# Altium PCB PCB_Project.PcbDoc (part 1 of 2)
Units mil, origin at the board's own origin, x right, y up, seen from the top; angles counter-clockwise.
Board outline 2890 x 2480 mil, 2 copper layers (Top Layer, Bottom Layer), stack 62 mil thick; 127 components, 89 nets, 394 pads, 87 vias.
Unrouted connection lines stored in the file: 1.
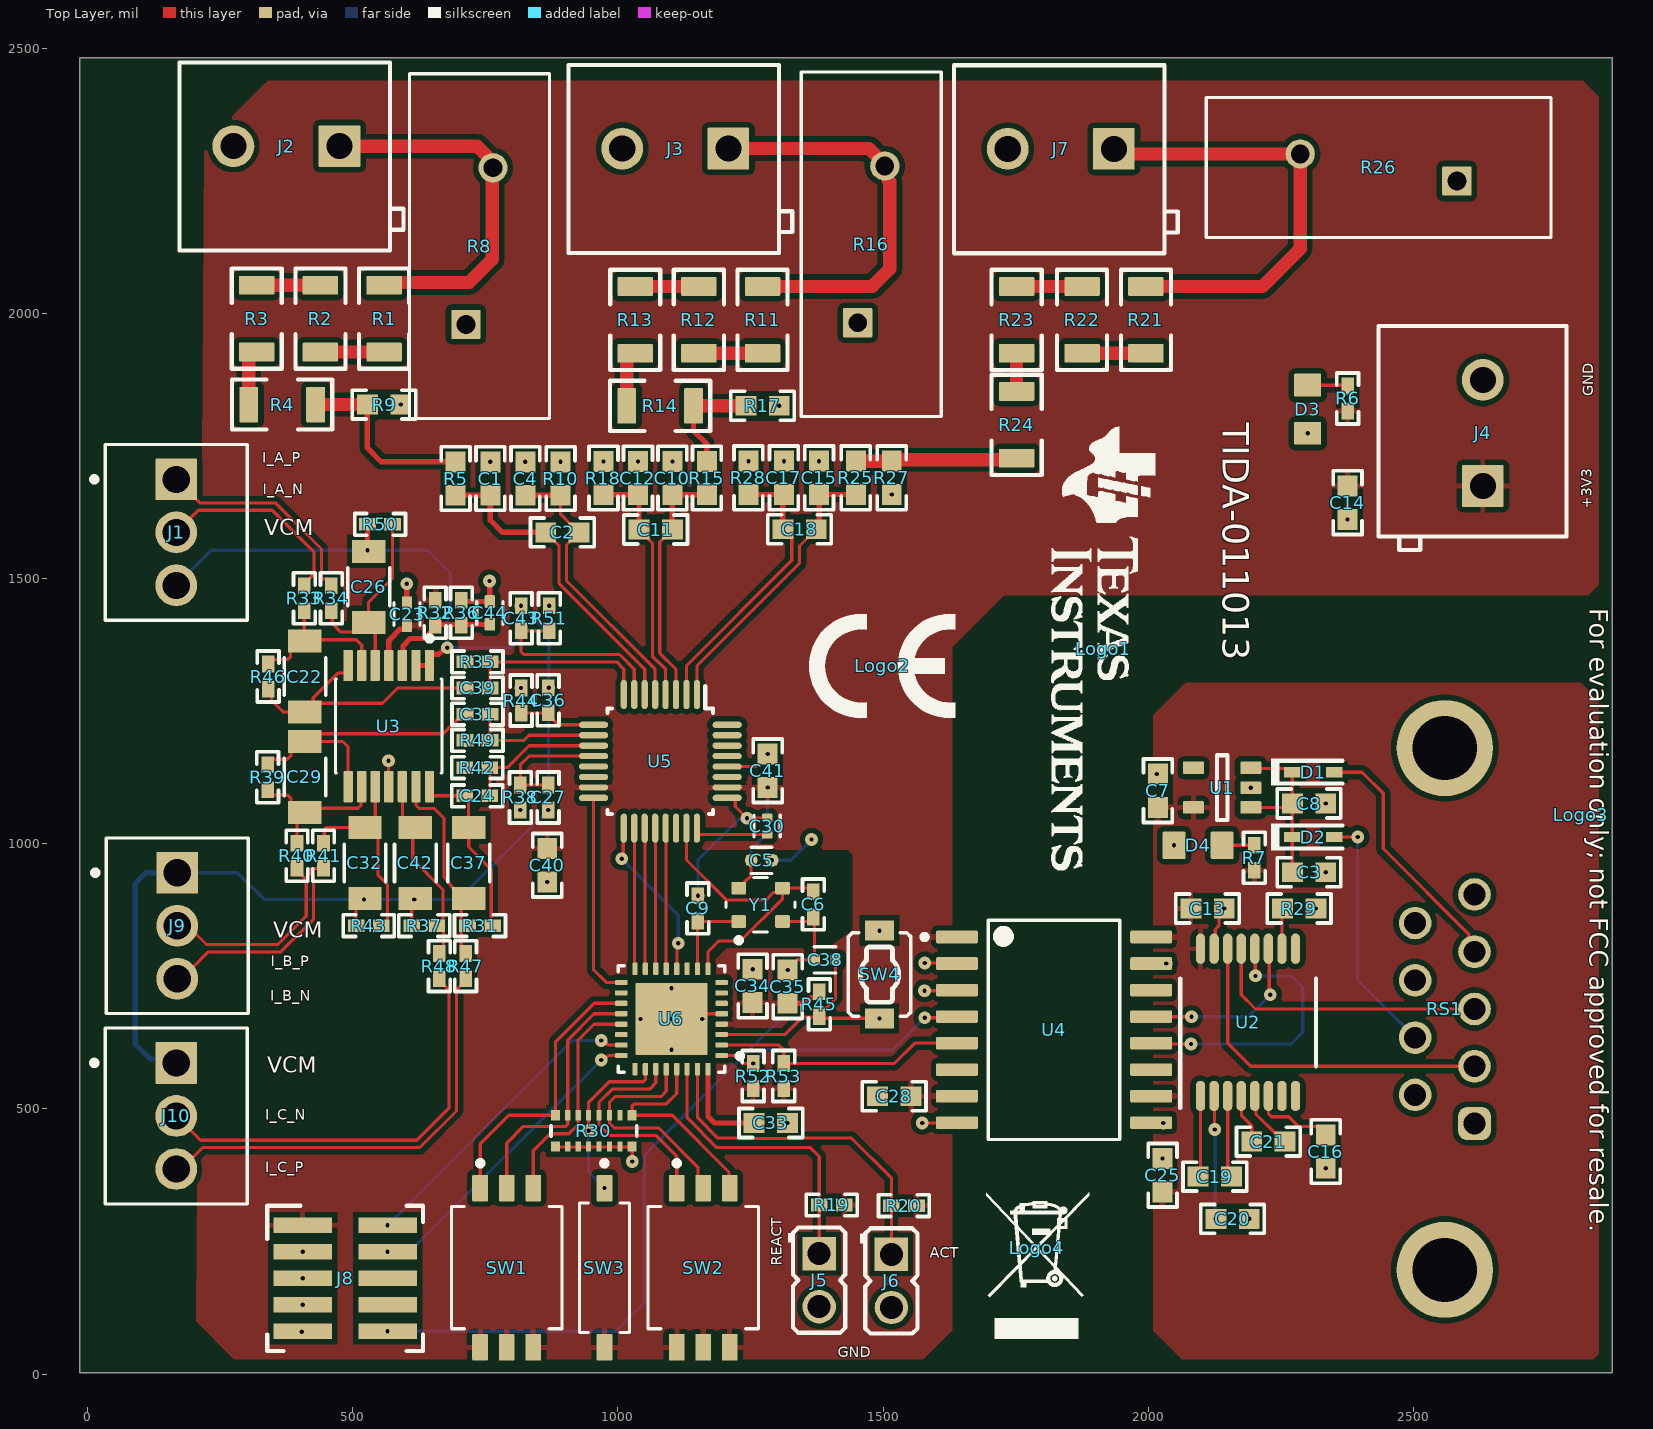
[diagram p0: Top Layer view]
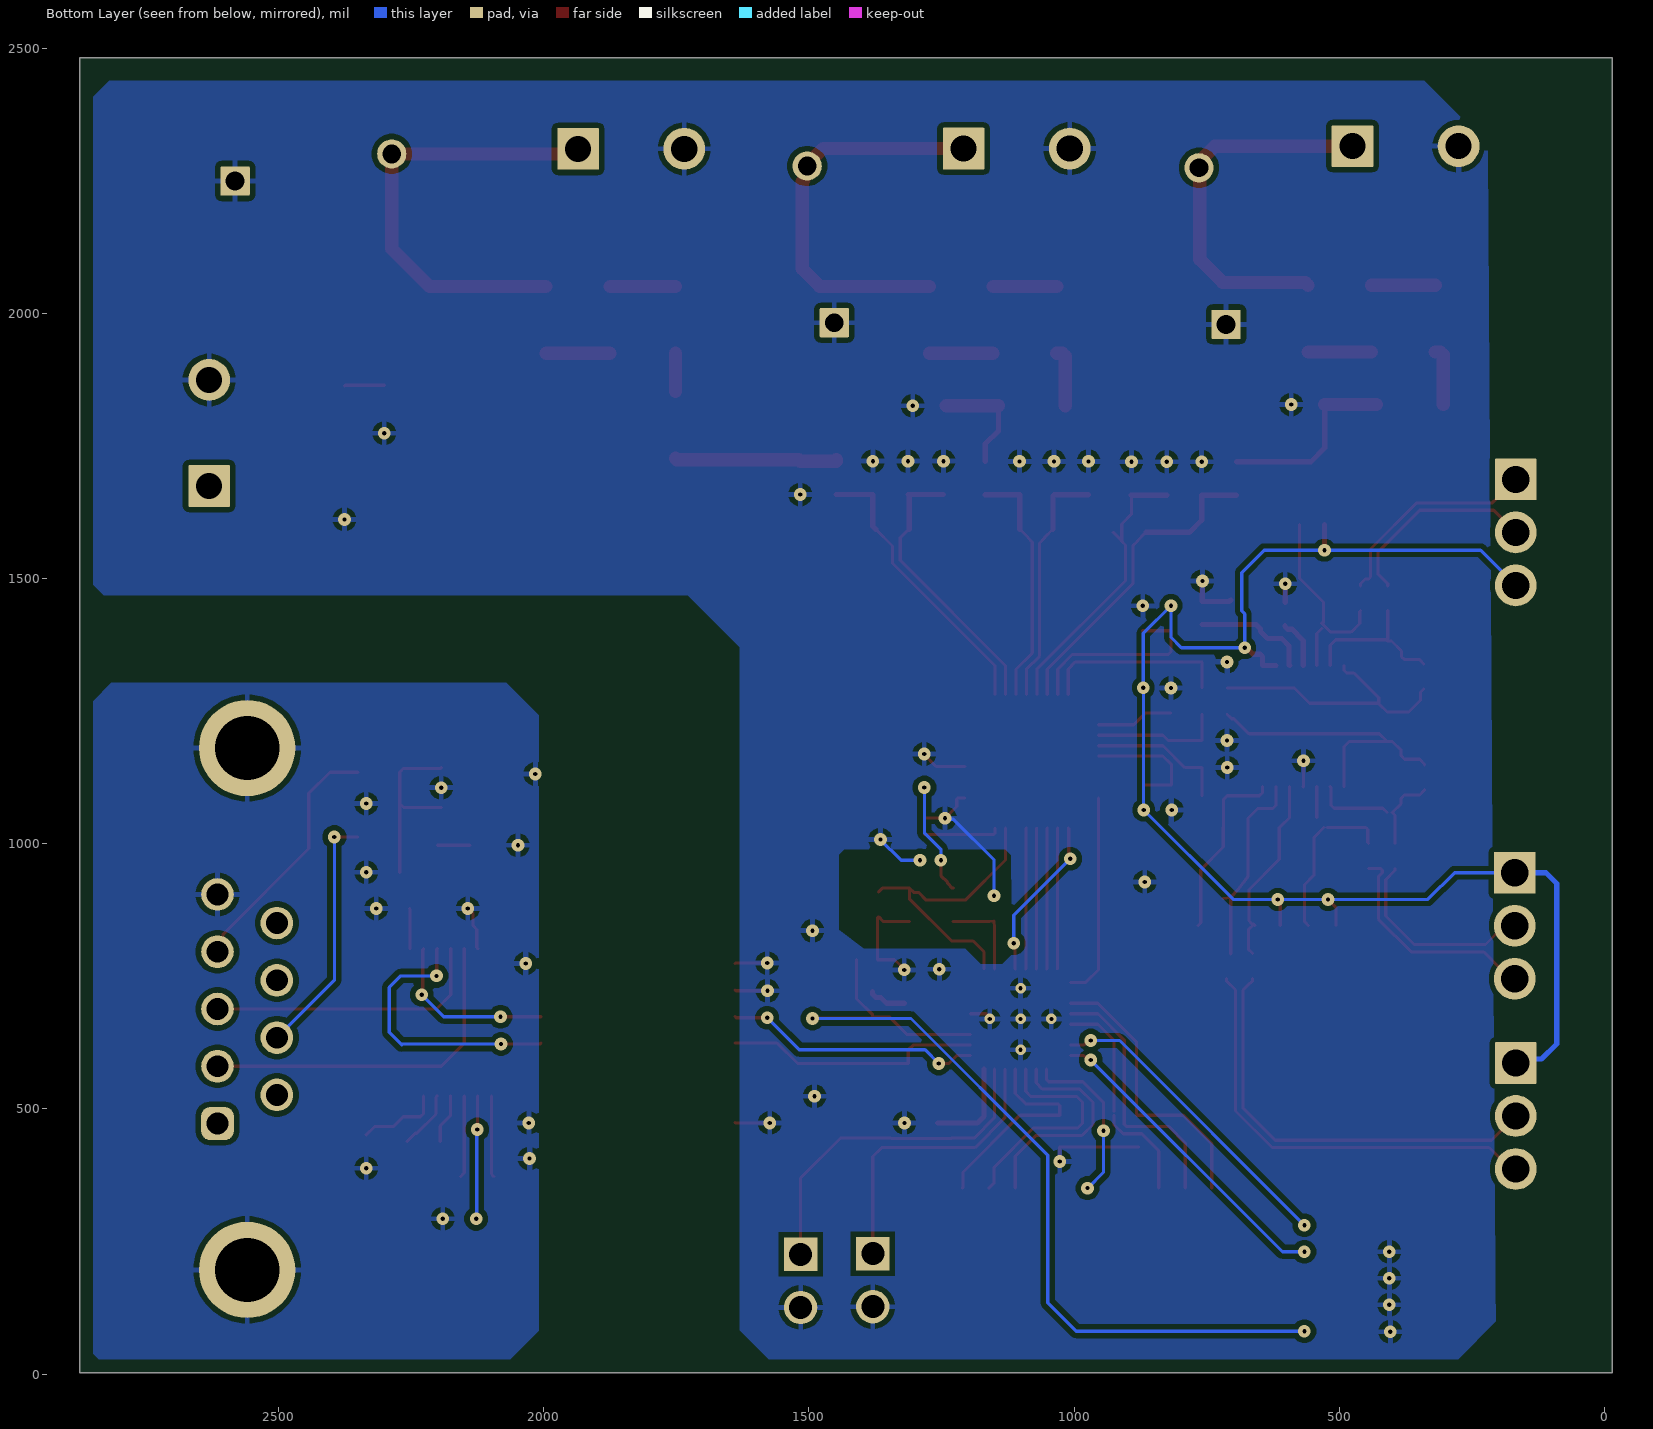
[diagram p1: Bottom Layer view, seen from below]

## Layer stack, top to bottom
Top Solder: solder mask 0.4, Solder Resist, Dk 3.5
Top Layer: signal copper 1.4
Dielectric1: core 59.2, FR-4 High Tg, Dk 4.8
Bottom Layer: signal copper 1.4
Bottom Solder: solder mask 0.4, Solder Resist, Dk 3.5

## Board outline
-15,2 -15,2482 2875,2482 2875,2

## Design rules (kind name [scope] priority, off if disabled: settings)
AcuteAngle [All] p1: minimum=4.50000000000000E+0001 checktracksonly=FALSE
AssemblyTestPointUsage [All] p1: valid=2
BoardOutlineClearance BoardOutlineClearance_MountingHoles [OnCopper and InComponentClass('Mounting Holes')] p1: gap=39.37 ignorepadtopadclearanceinfootprint=FALSE
BoardOutlineClearance BoardOutlineClearance_Poly [OnCopper and IsPoly] p2: gap=25 ignorepadtopadclearanceinfootprint=FALSE
BoardOutlineClearance [OnCopper and Not InComponentClass('Logo') and not InComponentClass('FiducialMark') and not InRegion(1000,500,4000,800) and not InPoly] p3: gap=40 ignorepadtopadclearanceinfootprint=FALSE
Clearance Clearance_Keepouts [((IsTrack Or IsArc) And Not InPoly) And IsFree and IsKeepOut vs ((IsTrack Or IsArc) And Not InPoly) And IsFree and IsKeepOut] p1: gap=0 ignorepadtopadclearanceinfootprint=FALSE
Clearance Clearance_Poly [InPolygon] p2: gap=10 ignorepadtopadclearanceinfootprint=TRUE
Clearance Clearance_FiducialMark [IsKeepOut and InComponentClass('FiducialMark') vs IsPad and InComponentClass('FiducialMark')] p3: gap=0 ignorepadtopadclearanceinfootprint=FALSE
Clearance [All] p4: gap=7.87 ignorepadtopadclearanceinfootprint=TRUE
ComponentClearance ComponentClearance_MountingHoles_FiducialMarks [InComponentClass('Mounting Holes') vs InComponentClass('FiducialMark')] p1: gap=50 collisioncheckmode=3 verticalgap=10 showdistances=FALSE
ComponentClearance ComponentClearance_Shunt [InComponentClass('Header') vs InComponentClass('Shunt')] p2: gap=0 collisioncheckmode=3 verticalgap=0 showdistances=FALSE
ComponentClearance ComponentClearance_Logo [InComponentClass('Logo')] p3: gap=30 collisioncheckmode=3 verticalgap=10 showdistances=FALSE
ComponentClearance ComponentClearance_ScrewToNut [(HasFootprint('NY PMS 440 0025 PH')) vs (HasFootprint('Keystone_1902C'))] p4: gap=5 collisioncheckmode=3 verticalgap=10 showdistances=FALSE
ComponentClearance ComponentClearance_MountingHoles [InComponentClass('Mounting Holes')] p5: gap=100 collisioncheckmode=3 verticalgap=100000 showdistances=FALSE
ComponentClearance ComponentClearance_SmallPassives [HasFootprint('0201*') or HasFootprint('0402*') or HasFootprint('0508') or HasFootprint('0603*') or HasFootprint('0612') or HasFootprint('0805*') or HasFootprint('0815*') or HasFootprint('0830*') or HasFootprint('1206*') or HasFootprint('1210*') or HasFootprint('1808*') or HasFootprint('1812*') or HasFootprint('1825*') or HasFootprint('2010*') or HasFootprint('2220*') or HasFootprint('2225*') or HasFootprint('2512*') or HasFootprint('2728*') or HasFootprint('3518*') vs HasFootprint('0201*') or HasFootprint('0402*') or HasFootprint('0508') or HasFootprint('0603*') or HasFootprint('0612') or HasFootprint('0805*') or HasFootprint('0815*') or HasFootprint('0830*') or HasFootprint('1206*') or HasFootprint('1210*') or HasFootprint('1808*') or HasFootprint('1812*') or HasFootprint('1825*') or HasFootprint('2010*') or HasFootprint('2220*') or HasFootprint('2225*') or HasFootprint('2512*') or HasFootprint('2728*') or HasFootprint('3518*')] p6: gap=14.96 collisioncheckmode=3 verticalgap=10 showdistances=FALSE
ComponentClearance ComponentClearance_THtoSMT [IsThruComponent vs IsSMTComponent] p7: gap=30 collisioncheckmode=3 verticalgap=30 showdistances=FALSE
ComponentClearance ComponentClearance_THtoTH [IsThruComponent vs IsThruComponent] p8: gap=20 collisioncheckmode=3 verticalgap=30 showdistances=FALSE
ComponentClearance [All] p9: gap=20 collisioncheckmode=3 verticalgap=10 showdistances=FALSE
DiffPairsRouting [All] p1: maxlimit=100 minlimit=10 mostfreqgap=10 toplayer_minwidth=15 toplayer_maxwidth=15 toplayer_prefwidth=15 bottomlayer_minwidth=15 bottomlayer_maxwidth=15 bottomlayer_prefwidth=15 maxuncoupledlength=1000
FabricationTestPointUsage TestPointUsage [All] p1: valid=2 allowmultiple=FALSE
FabricationTestpoint Testpoint [All] p1: side=3 testpointundercomponent=TRUE minsize=40 maxsize=100 preferedsize=60 minholesize=0 maxholesize=40 preferedholesize=32 testpointgrid=1 allowsidetop=TRUE allowsidebottom=TRUE usegrid=TRUE gridtolerance=0.01
FanoutControl Fanout_LCC [IsLCC] p1: bgadir=Out bgaviamode=Centered fanoutstyle=Auto fanoutdirection=Alternating viagrid=1 // Fanout_LCC (Default Rule)
FanoutControl Fanout_BGA [IsBGA] p2: bgadir=Out bgaviamode=Centered fanoutstyle=Auto fanoutdirection=Alternating viagrid=1 // Fanout_BGA (Default Rule)
FanoutControl Fanout_Default [All] p4: bgadir=Out bgaviamode=Centered fanoutstyle=Auto fanoutdirection=Alternating viagrid=1 // Fanout_Default (Default Rule)
FanoutControl Fanout_Small [(CompPinCount < 5)] p5: bgadir=Out bgaviamode=Centered fanoutstyle=Auto fanoutdirection=OutThenIn viagrid=1 // Fanout_Small (Default Rule)
HoleSize [All] p1: absolutevalues=TRUE maxlimit=251 minlimit=7.87 maxpercent=80.000 minpercent=20.000
MinimumAnnularRing MinimumAnnularRing_ThermalPadVias [IsVia and InAnyComponent] p1: minimumring=5.91
MinimumAnnularRing [All] p2: minimumring=7.87
MinimumSolderMaskSliver MinimumSolderMaskSliver_Logo [InComponentClass('Logo') vs InComponentClass('Logo')] p1: minsoldermaskwidth=0.7
MinimumSolderMaskSliver [All] p2: minsoldermaskwidth=3.94
PlaneConnect [All] p1: planeconnectstyle=Relief reliefexpansion=10 reliefentries=4 reliefconductorwidth=10 reliefairgap=10
PolygonConnect [All] p1: connectstyle=Relief reliefconductorwidth=10 reliefentries=4 polygonreliefangle="90 Angle" airgapwidth=10
RoutingVias ThermalPadVias [IsVia and InAnyComponent] p1: holewidth=7.87 width=19.68 viastyle="Through Hole" minholewidth=7.87 minwidth=19.68 maxholewidth=12.99 maxwidth=23.62
RoutingVias [All] p2: holewidth=16 width=34 viastyle="Through Hole" minholewidth=7.87 minwidth=24 maxholewidth=40 maxwidth=65
SilkToBoardRegionClearance [Not ((IsComment or IsDesignator) And (Hide <> 'False')) and not InRegion(1000,500,4000,800)] p1:
SilkToSilkClearance SilkToSilkClearance_Pb-FreeLogo [(HasFootprint('Pb-Free_Overlay_Medium') OR HasFootprint('Pb-Free_Overlay_Small')) vs (HasFootprint('Pb-Free_Overlay_Medium') OR HasFootprint('Pb-Free_Overlay_Small'))] p1: silktosilkclearance=0
SilkToSilkClearance [All] p2: silktosilkclearance=3.94
SilkToSolderMaskClearance SilkToComponentPadClearance [(IsPad or IsFill or IsRegion) and InAnycomponent] p1: minsilkscreentomaskgap=5 clearancetoexposedcopper=TRUE
SilkToSolderMaskClearance "Silk to Solder Mask Opening" [All] p2: minsilkscreentomaskgap=3.94 clearancetoexposedcopper=FALSE
SolderMaskExpansion [All] p1: expansion=1.97 istentingtop=FALSE
SupplyNets "Schematic Supply Nets_45" [InNet('VG2')] p1: voltage=0.000
SupplyNets "Schematic Supply Nets_44" [InNet('VG4')] p2: voltage=0.000
SupplyNets "Schematic Supply Nets_43" [InNet('V_Phase_A_P')] p3: voltage=0.000
SupplyNets "Schematic Supply Nets_42" [InNet('VG1')] p4: voltage=0.000
SupplyNets "Schematic Supply Nets_41" [InNet('IN_Phase_C')] p5: voltage=0.000
SupplyNets "Schematic Supply Nets_40" [InNet('nRST')] p6: voltage=0.000
SupplyNets "Schematic Supply Nets_39" [InNet('V_Phase_B_N')] p7: voltage=0.000
SupplyNets "Schematic Supply Nets_38" [InNet('V_Phase_C_P')] p8: voltage=0.000
SupplyNets "Schematic Supply Nets_37" [InNet('Serial_RX')] p9: voltage=0.000
SupplyNets "Schematic Supply Nets_36" [InNet('RS232_PORT_DTR')] p10: voltage=0.000
SupplyNets "Schematic Supply Nets_35" [InNet('HFXOUT')] p11: voltage=0.000
SupplyNets "Schematic Supply Nets_34" [InNet('Serial_RX_ISO')] p12: voltage=0.000
SupplyNets "Schematic Supply Nets_33" [InNet('VCM')] p13: voltage=0.000
SupplyNets "Schematic Supply Nets_32" [InNet('SPI_SCK')] p14: voltage=0.000
SupplyNets "Schematic Supply Nets_31" [InNet('IP_Phase_B')] p15: voltage=0.000
SupplyNets "Schematic Supply Nets_30" [InNet('V_Phase_B_P')] p16: voltage=0.000
SupplyNets "Schematic Supply Nets_29" [InNet('Meter_TX_PC_RX')] p17: voltage=0.000
SupplyNets "Schematic Supply Nets_28" [InNet('ADS_SYNC_RESET')] p18: voltage=0.000
SupplyNets "Schematic Supply Nets_27" [InNet('Serial_TX')] p19: voltage=0.000
SupplyNets "Schematic Supply Nets_26" [InNet('VCC_ISO_RS')] p20: voltage=0.000
SupplyNets "Schematic Supply Nets_25" [InNet('IG1')] p21: voltage=0.000
SupplyNets "Schematic Supply Nets_24" [InNet('HFXIN')] p22: voltage=0.000
SupplyNets "Schematic Supply Nets_22" [InNet('IP_Phase_C')] p23: voltage=0.000
SupplyNets "Schematic Supply Nets_21" [InNet('IG2')] p24: voltage=0.000
SupplyNets "Schematic Supply Nets_20" [InNet('M0_CLKOUT')] p25: voltage=0.000
SupplyNets "Schematic Supply Nets_19" [InNet('V_Phase_A_N')] p26: voltage=0.000
SupplyNets "Schematic Supply Nets_18" [InNet('VCC')] p27: voltage=0.000
SupplyNets "Schematic Supply Nets_17" [InNet('ADS_DIN_MSP_DOUT')] p28: voltage=0.000
SupplyNets "Schematic Supply Nets_16" [InNet('IP_Phase_A')] p29: voltage=0.000
SupplyNets "Schematic Supply Nets_15" [InNet('ADS_DOUT_MSP_DIN')] p30: voltage=0.000
SupplyNets "Schematic Supply Nets_14" [InNet('TPS709_IN')] p31: voltage=0.000
SupplyNets "Schematic Supply Nets_13" [InNet('GND_ISO_RS')] p32: voltage=0.000
SupplyNets "Schematic Supply Nets_12" [InNet('REACT')] p33: voltage=0.000
SupplyNets "Schematic Supply Nets_11" [InNet('SW_INT')] p34: voltage=0.000
SupplyNets "Schematic Supply Nets_10" [InNet('IN_Phase_A')] p35: voltage=0.000
SupplyNets "Schematic Supply Nets_9" [InNet('RS232_PORT_RTS')] p36: voltage=0.000
SupplyNets "Schematic Supply Nets_8" [InNet('IN_Phase_B')] p37: voltage=0.000
SupplyNets "Schematic Supply Nets_7" [InNet('Meter_RX_PC_TX')] p38: voltage=0.000
SupplyNets "Schematic Supply Nets_6" [InNet('Serial_TX_ISO')] p39: voltage=0.000
SupplyNets "Schematic Supply Nets_5" [InNet('ACT')] p40: voltage=0.000
SupplyNets "Schematic Supply Nets_4" [InNet('IG4')] p41: voltage=0.000
SupplyNets "Schematic Supply Nets_3" [InNet('GND')] p42: voltage=0.000
SupplyNets "Schematic Supply Nets_2" [InNet('V_Phase_C_N')] p43: voltage=0.000
SupplyNets "Schematic Supply Nets_1" [InNet('ADS_CS')] p44: voltage=0.000
SupplyNets "Schematic Supply Nets" [InNet('ADS_DRDY')] p45: voltage=0.000
UnRoutedNet [All] p1: checkbadconnections=TRUE
Width [All] p1: maxlimit=100 minlimit=6 preferedwidth=10 checkconnectedcopper=TRUE
14 further rules are at their usual default settings.

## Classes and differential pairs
component class Header: J5 J6
component class Logo: Logo1
component class PCB_Project_Hardware: Logo1 Logo2 Logo3 Logo4

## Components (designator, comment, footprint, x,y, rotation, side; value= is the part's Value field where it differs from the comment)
C1 "GCM1885C2A100JA16D" 0603 759.46,1688.33 r90 top value=10pF
C2 "CGA3EANP02A682J080AC" 0603 895.3,1586.85 r0 top value=6800pF
C3 "GRT188R61H225KE13D" 0603 2303.04,946.1 r0 top value=2.2uF
C4 "GCM1885C2A100JA16D" 0603 825.41,1688.33 r270 top value=10pF
C5 "885012205018" FP-885012205018_0402-MFG 1270.79,968.56 r180 top value=100nF
C6 "GRM1555C1H150JA01D" 0402 1368.57,885.42 r270 top value=15pF
C7 "GRT188R61H225KE13D" 0603 2018.09,1099.66 r90 top value=2.2uF
C8 "CGA3E1X7R1E105M080AC" 0603 2303.04,1075.59 r0 top value=1uF
C9 "GRM1555C1H150JA01D" 0402 1150.82,877.89 r270 top value=15pF
C10 "GCM1885C2A100JA16D" 0603 1102.67,1689.21 r90 top value=10pF
C11 "CGA3EANP02A682J080AC" 0603 1071.17,1592.23 r180 top value=6800pF
C12 "GCM1885C2A100JA16D" 0603 1037.78,1689.21 r270 top value=10pF
C13 "CGA3E2X8R1E104K080AA" 0603 2111.64,877.64 r180 top value=0.1uF
C14 "GRM188R61A106KAALD" 0603 2375.71,1642.79 r270 top value=10uF
C15 "GCM1885C2A100JA16D" 0603 1379.33,1689.66 r90 top value=10pF
C16 "CGA3E2X8R1E104K080AA" 0603 2334.54,419.44 r90 top value=0.1uF
C17 "GCM1885C2A100JA16D" 0603 1312.91,1689.66 r270 top value=10pF
C18 "CGA3EANP02A682J080AC" 0603 1342.4,1592.68 r180 top value=6800pF
C19 "CGA3E2X8R1E104K080AA" 0603 2125.34,372.28 r180 top value=0.1uF
C20 "CGA3E2X8R1E104K080AA" 0603 2158.85,292.56 r180 top value=0.1uF
C21 "CGA3E2X8R1E104K080AA" 0603 2226.4,438.14 r180 top value=0.1uF
C22 "GRM31C5C1H683JA01L" 1206_180 409.87,1315.09 r90 top value=0.068uF
C23 "KAM05CR71A105MH" FP-KAM05CR71A105MH_0402-MFG 602.3,1432.91 r90 top value=1µF
C24 "GRM155R61E105KA12D" 0402 734.91,1090.19 r0 top value=1uF
C25 "C0603X104K3RACTU" 0603 2026.87,374.75 r90 top value=0.1uF
C26 "GRM31C5C1H683JA01L" 1206_180 530,1484.25 r270 top value=0.068uF
C27 "GRM155R61E105KA12D" 0402 868.54,1087.07 r90 top value=1uF
C28 "C0603X104K3RACTU" 0603 1520.81,523.56 r180 top value=0.1uF
C29 "GRM31C5C1H683JA01L" 1206_180 409.88,1125.62 r270 top value=0.068uF
C30 "CGA2B2X7R1C224K050BE" FP-CGA2B2X7R1C224K050BE_0402-MFG 1281.38,1033.1 r90 top value=220nF
C31 "GRM155R61E105KA12D" 0402 735.3,1244.23 r0 top value=1uF
C32 "GRM31C5C1H683JA01L" 1206_180 523.05,963.69 r90 top value=0.068uF
C33 "GRM188R61A474KA61D" 0603 1288.27,473.36 r180 top value=0.47uF
C34 "GRM188R61A106KAALD" 0603 1253.98,731.61 r270 top value=10uF
C35 "CGA3E2X8R1E104K080AA" 0603 1320,730.46 r270 top value=0.1uF
C36 "GRM155R61E105KA12D" 0402 868.54,1270.26 r270 top value=1uF
C37 "GRM31C5C1H683JA01L" 1206_180 718.68,963.69 r270 top value=0.068uF
C38 "885012205050" FP-885012205050_0402-MFG 1390.51,780.93 r0 top value=10nF
C39 "GRM155R61E105KA12D" 0402 735.3,1293.44 r0 top value=1uF
C40 "CGA3E1X7R1C105K080AC" 0603 866.71,959.28 r90 top value=1uF
C41 "CGA3E1X7R1C105K080AC" 0603 1282.28,1137.43 r270 top value=1uF
C42 "GRM31C5C1H683JA01L" 1206_180 618.05,963.69 r90 top value=0.068uF
C43 "GRM155R61E105KA12D" 0402 817.32,1425.03 r270 top value=1uF
C44 "KAM05CR71A105MH" FP-KAM05CR71A105MH_0402-MFG 758.53,1434.87 r90 top value=1µF
D1 "1N4148WT" Fairchild_SOD-523F 2310.92,1134.71 r0 top value=75V
D2 "1N4148WT" Fairchild_SOD-523F 2310.92,1012.48 r0 top value=75V
D3 "CMD17-21SRC/TR8" CMD17-21_Red 2300.44,1819.01 r270 top value=Red
D4 "CMD17-21SRC/TR8" CMD17-21_Red 2093.89,996.86 r180 top value=Red
J1 "691210910003" FP-691210910003_HDR3-MFG 167.21,1586.85 r270 top
J2 "ED120/2DS" On-Shore_ED120_2DS 375,2315 r180 top
J3 "ED120/2DS" On-Shore_ED120_2DS 1108.13,2310.43 r180 top
J4 "ED120/2DS" On-Shore_ED120_2DS 2630.71,1774.29 r90 top
J5 "961102-6404-AR" 3M_961102-6404-AR 1379.49,176.84 r270 top
J6 "961102-6404-AR" 3M_961102-6404-AR 1515.49,175.46 r270 top
J7 "ED120/2DS" On-Shore_ED120_2DS 1835,2310 r180 top
J8 "FTSH-105-01-L-DV-K" Samtec_FTSH-105-01-x-DV-K 485.65,180.46 r0 top
J9 "691210910003" FP-691210910003_HDR3-MFG 169.18,845.17 r270 top
J10 "691210910003" FP-691210910003_HDR3-MFG 167.21,486.54 r270 top
Logo1 "Texas Instruments" TI_Stacked_Overlay_Small 1915.13,1367.77 r270 top
Logo2 "CE Mark" CE_Mark_5mm 1498.26,1334.93 r0 top
Logo3 "FCC disclaimer" FCC_disclaimer 2815.5,1054.64 r270 top
Logo4 "WEEE logo" WEEE_Minimum 1789.5,238.46 r0 top
R1 "TNPV1206330KBEEN" TNPV1206 559.02,1989.83 r90 top value=330k
R2 "TNPV1206330KBEEN" TNPV1206 439.02,1989.83 r270 top value=330k
R3 "TNPV1206330KBEEN" TNPV1206 319.02,1989.83 r90 top value=330k
R4 "TNPV1206330KBEEN" TNPV1206 367.01,1827.82 r180 top value=330k
R5 "RT0603DRD071KL" 0603 693.84,1688.33 r270 top value=1.00k
R6 "RC0402FR-07470RL" 0402 2375.71,1839.29 r270 top value=470
R7 "RC0402FR-07470RL" 0402 2200.14,973.24 r270 top value=470
R8 "820542711" FP-820542711_RADIAL-MFG 738.87,2126.63 r90 top
R9 "RC0603FR-071KL" 0603 559.02,1827.82 r180 top value=1.00k
R10 "RT0603DRD071KL" 0603 891.9,1688.33 r270 top value=1.00k
R11 "TNPV1206330KBEEN" TNPV1206 1272.63,1987.47 r90 top value=330k
R12 "TNPV1206330KBEEN" TNPV1206 1152.63,1987.47 r270 top value=330k
R13 "TNPV1206330KBEEN" TNPV1206 1032.63,1987.47 r90 top value=330k
R14 "TNPV1206330KBEEN" TNPV1206 1079.63,1825.46 r180 top value=330k
R15 "RT0603DRD071KL" 0603 1167.63,1689.21 r270 top value=1.00k
R16 "820542711" FP-820542711_RADIAL-MFG 1477.61,2129.88 r90 top
R17 "RC0603FR-071KL" 0603 1272.63,1825.46 r180 top value=1.00k
R18 "RT0603DRD071KL" 0603 972.67,1689.21 r270 top value=1.00k
R19 "CRCW040247K0JNED" 0402 1403.11,318.65 r0 top value=47k
R20 "CRCW040247K0JNED" 0402 1539.11,317.28 r0 top value=47k
R21 "TNPV1206330KBEEN" TNPV1206 1995.47,1987.47 r90 top value=330k
R22 "TNPV1206330KBEEN" TNPV1206 1875,1987.47 r270 top value=330k
R23 "TNPV1206330KBEEN" TNPV1206 1751.69,1987.47 r90 top value=330k
R24 "TNPV1206330KBEEN" TNPV1206 1751.69,1789.67 r90 top value=330k
R25 "RT0603DRD071KL" 0603 1448.54,1689.66 r270 top value=1.00k
R26 "820542711" FP-820542711_RADIAL-MFG 2434.1,2274.87 r180 top
R27 "RC0603FR-071KL" 0603 1516.34,1689.66 r90 top value=1.00k
R28 "RT0603DRD071KL" 0603 1246.01,1689.66 r270 top value=1.00k
R29 "CRCW06034K70JNEA" 0603 2284.35,877.64 r180 top value=4.7k
R30 "EXB2HV103JV" RESCAXS_EXB-2HV 954.5,458.46 r180 top value=10k
R31 "RMCF0402FT1M00" 0402 740,845.46 r0 top value=1.00Meg
R32 "RG1005P-104-B-T5" 0402 655.45,1435.46 r90 top value=100k
R33 "ERA-2AEB102X" 0402 408.63,1462.6 r270 top value=1.00k
R34 "ERA-2AEB102X" 0402 459.87,1462.6 r270 top value=1.00k
R35 "CRCW0402301KFKED" 0402 735.3,1342.65 r0 top value=301k
R36 "RG1005P-104-B-T5" 0402 704.69,1435.46 r270 top value=100k
R37 "RMCF0402FT1M00" 0402 635,845.46 r180 top value=1.00Meg
R38 "CRCW0402301KFKED" 0402 816.03,1087.07 r270 top value=301k
R39 "RMCF0402FT1M00" 0402 339.38,1125.19 r90 top value=1.00Meg
R40 "ERA-2AEB102X" 0402 394.88,977 r90 top value=1.00k
R41 "ERA-2AEB102X" 0402 444.88,977 r90 top value=1.00k
R42 "CRCW0402301KFKED" 0402 734.91,1143.33 r0 top value=301k
R43 "RMCF0402FT1M00" 0402 530,845.46 r180 top value=1.00Meg
R44 "CRCW0402301KFKED" 0402 817.32,1269.82 r90 top value=301k
R45 "CRCW040247K0JNED" 0402 1379.91,696.96 r90 top value=47k
R46 "RMCF0402FT1M00" 0402 340.57,1315.09 r270 top value=1.00Meg
R47 "ERA-2AEB102X" 0402 712.88,769.12 r90 top value=1.00k
R48 "ERA-2AEB102X" 0402 663.4,769.12 r90 top value=1.00k
R49 "CRCW0402301KFKED" 0402 735.3,1194.52 r0 top value=301k
R50 "RMCF0402FT1M00" 0402 551.52,1601.85 r180 top value=1.00Meg
R51 "CRCW0402301KFKED" 0402 870.56,1425.03 r90 top value=301k
R52 "PCF0402-12-10KBT1" 0402 1255,561.84 r270 top value=10.0k
R53 "PCF0402-12-10KBT1" 0402 1312.65,561.84 r270 top value=10.0k
RS1 "2-5747706-0" TE_2-5747706-0 2559,688.22 r270 top
SW1 "416131160803" FP-416131160803_SMT_SW_5MM8_4MM98-MFG 790.28,200.46 r270 top
SW2 "416131160803" FP-416131160803_SMT_SW_5MM8_4MM98-MFG 1160.84,200.46 r270 top
SW3 "TDA01H0SB1R" FP-TDA01H0SB1R_SMT_SW_2MM40_6MM20-MFG 974.5,200.46 r270 top
SW4 "TL1015AF160QG" SW_TL1015AF160QG 1493.25,753.27 r270 top
U1 "TPS70933DBVR" DBV0005A_N 2139.16,1105.56 r180 top
U2 "TRS3232EIDBR" DB0016A_L 2188.02,663.07 r90 top
U3 "TLV4387PWR" PW0014A-MFG 567.99,1221.54 r270 top
U4 "ISO6731DWR" DW0016A-MFG 1822.22,648.96 r0 top
U5 "ADS131M08IPBSR" PBS0032A_N 1080,1155.15 r270 top
U6 "MSPM0G1506SRHB" RHB0032N-MFG 1100.91,669.4 r180 top
Y1 "CDC6CE008192ADLE" DLE0004A-MFG 1268.97,884.67 r90 top

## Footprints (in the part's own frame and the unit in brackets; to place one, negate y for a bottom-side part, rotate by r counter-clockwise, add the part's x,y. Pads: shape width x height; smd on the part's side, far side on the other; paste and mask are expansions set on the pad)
3M_961102-6404-AR [mm] "Header, 2.54mm, 2x1, TH"
  rect 1.6x1.6 hole 1.1: 1(-1.27,0)
  round 1.6 hole 1.1: 2(1.27,0)
  silkscreen extent -2.52,-1.5 2.52,1.25, body extent -2.52,-1.25 2.52,1.25, height 8.5
0402 [mm] "0402 from SM-752 data"
  rect 0.8x0.6 smd: 1(-0.6,0) 2(0.6,0)
  silkscreen extent -1.22,-0.52 1.22,0.52, body extent -0.55,-0.3 0.55,0.3, height 0.6
0603 [mm] "0603 from SM-752 data"
  rect 1x0.95 smd: 1(-0.8,0) 2(0.8,0)
  silkscreen extent -1.52,-0.69 1.52,0.69, body extent -0.87,-0.47 0.87,0.47, height 1
1206_180 [mm] "1206_180"
  rect 1.1x1.6 smd: 1(-1.7,0) 2(1.7,0)
  silkscreen extent -0.9,-1 0.9,1, body extent -1.75,-0.95 1.75,0.95, height 1.8
CE_Mark_5mm [mil] "Minimum text height for CE Mark"
  silkscreen extent -138,-98 138,98
CMD17-21_Red [mm] "SMD, 2-Leads, Body 2x1.25mm"
  rrect9% 1.1x1.3 smd: 1(-1.15,0) 2(1.15,0)
  body extent -1,-0.62 1,0.62, height 1.09
DB0016A_L [mm] "SOP, 16-Leads, Body 6.2x5.3mm, Pitch 0.65mm, IPC High Density"
  oval 1.45x0.45 smd: 1(-3.525,2.275) 2(-3.525,1.625) 3(-3.525,0.975) 4(-3.525,0.325) 5(-3.525,-0.325) 6(-3.525,-0.975) 7(-3.525,-1.625) 8(-3.525,-2.275) 9(3.525,-2.275) 10(3.525,-1.625) 11(3.525,-0.975) 12(3.525,-0.325) 13(3.525,0.325) 14(3.525,0.975) 15(3.525,1.625) 16(3.525,2.275)
  silkscreen extent -4.1,-3.25 2.1,3.25, body extent -3.91,-3.1 3.91,3.1, height 2
DBV0005A_N [mm] "SOT23, 5-Leads, Body 2.9x1.6mm, Pitch 0.95mm, Lead Span 2.8mm, IPC Medium Density"
  rrect17% 1x0.6 smd: 1(-1.375,0.95) 2(-1.375,0) 3(-1.375,-0.95) 4(1.375,-0.95) 5(1.375,0.95)
  silkscreen extent -0.25,-1.55 0.25,1.55, body extent -1.42,-1.46 1.42,1.46, height 1.09
DLE0004A-MFG [mm]
  rrect17% 0.6x0.7 smd paste-1000 mask+0: 1(-0.8,1.05) 2(-0.8,-1.05) 3(0.8,-1.05) 4(0.8,1.05)
  silkscreen extent -1.82,-1.65 1.3,1.65, body extent -1.4,-1.75 1.4,1.75, height 0.25
DW0016A-MFG [mm]
  rrect17% 2x0.6 smd paste+0 mask+0: 1(-4.65,4.445) 2(-4.65,3.175) 3(-4.65,1.905) 4(-4.65,0.635) 5(-4.65,-0.635) 6(-4.65,-1.905) 7(-4.65,-3.175) 8(-4.65,-4.445) 9(4.65,-4.445) 10(4.65,-3.175) 11(4.65,-1.905) 12(4.65,-0.635) 13(4.65,0.635) 14(4.65,1.905) 15(4.65,3.175) 16(4.65,4.445)
  silkscreen extent -6.32,-5.25 3.15,5.25, body extent -5.75,-5.35 5.75,5.35, height 0.25
Fairchild_SOD-523F [mm] "SMD, 2-Leads, Body 1.2x0.8mm"
  rect 0.8x0.5 smd: 1(-1,0) 2(1,0)
  silkscreen extent -2.03,-0.65 1.4,0.65, body extent -0.65,-0.45 0.65,0.45, height 0.7
FCC_disclaimer [mil]
FP-820542711_RADIAL-MFG [mm] "Recommended Land Pattern"
  rrect7% 1.4x1.4 hole 0.9 paste-2539.97 mask+0: 1(-3.75,0.65)
  round 1.4 hole 0.9 paste-2539.97 mask+0: 2(3.75,-0.65)
  silkscreen extent -8.25,-3.35 8.25,3.35, body extent -8.25,-3.35 8.25,3.35, height 20
FP-416131160803_SMT_SW_5MM8_4MM98-MFG [mm]
  rrect13% 1.27x0.76 smd paste+0 mask+0: 1(-3.81,-1.27) 2(-3.81,0) 3(-3.81,1.27) 4(3.81,1.27) 5(3.81,0) 6(3.81,-1.27)
  silkscreen extent -5.12,-2.64 2.93,2.64, body extent -4.22,-2.49 4.22,2.49, height 2.65
FP-691210910003_HDR3-MFG [mm]
  rrect5% 2x2 hole 1.3 paste-2539.97 mask+0: 1(-2.54,0)
  round 2 hole 1.3 paste-2539.97 mask+0: 2(0,0) 3(2.54,0)
  silkscreen extent -4.21,-4.05 4.21,3.4, body extent -4.31,-3.5 4.31,3.5, height 0.25
FP-885012205018_0402-MFG [mm]
  rrect20% 0.5x0.5 smd paste+0 mask+0: 1(-0.5,0) 2(0.5,0)
  silkscreen extent -0.5,-0.63 0.5,0.63, body extent -0.85,-0.37 0.85,0.38, height 0.25
FP-885012205050_0402-MFG [mm]
  rrect20% 0.5x0.5 smd paste+0 mask+0: 1(-0.5,0) 2(0.5,0)
  silkscreen extent -0.53,-0.63 0.53,0.63, body extent -0.85,-0.38 0.85,0.38, height 0.25
FP-CGA2B2X7R1C224K050BE_0402-MFG [mm]
  rrect25% 0.4x0.5 smd paste+0 mask+0: 1(-0.4,0) 2(0.4,0)
  silkscreen extent -0.52,-0.63 0.53,0.63, body extent -0.7,-0.38 0.7,0.38, height 0.25
FP-KAM05CR71A105MH_0402-MFG [mm] "Recommended Land Pattern"
  rrect20% 0.6x0.5 smd paste+0 mask+0: 1(-0.55,0) 2(0.55,0)
  silkscreen extent -0.55,-0.63 0.55,0.63, body extent -0.95,-0.4 0.95,0.4, height 0.25
FP-TDA01H0SB1R_SMT_SW_2MM40_6MM20-MFG [mm]
  rrect13% 1.27x0.76 smd paste+0 mask+0: 1(-3.81,0) 2(3.81,0)
  silkscreen extent -5.12,-1.2 3.1,1.2, body extent -4.54,-1.3 4.54,1.3, height 0.25
On-Shore_ED120_2DS [mm] "ONSHORE"
  rrect5% 2x2 hole 1.25: 1(-2.54,0)
  round 2 hole 1.25: 2(2.54,0)
  silkscreen extent -5.6,-4 5.12,5, body extent -5.78,-4 5.08,5, height 13
PBS0032A_N [mm]
  oval 1.4x0.3 smd: 1(-3.2,1.75) 2(-3.2,1.25) 3(-3.2,0.75) 4(-3.2,0.25) 5(-3.2,-0.25) 6(-3.2,-0.75) 7(-3.2,-1.25) 8(-3.2,-1.75) 17(3.2,-1.75) 18(3.2,-1.25) 19(3.2,-0.75) 20(3.2,-0.25) 21(3.2,0.25) 22(3.2,0.75) 23(3.2,1.25) 24(3.2,1.75)
  oval 0.3x1.4 smd: 9(-1.75,-3.2) 10(-1.25,-3.2) 11(-0.75,-3.2) 12(-0.25,-3.2) 13(0.25,-3.2) 14(0.75,-3.2) 15(1.25,-3.2) 16(1.75,-3.2) 25(1.75,3.2) 26(1.25,3.2) 27(0.75,3.2) 28(0.25,3.2) 29(-0.25,3.2) 30(-0.75,3.2) 31(-1.25,3.2) 32(-1.75,3.2)
  silkscreen extent -3.6,-2.53 2.53,2.53, body extent -3.5,-3.5 3.5,3.5, height 1.12
PW0014A-MFG [mm] "Recommended Land Pattern"
  rrect22% 1.5x0.45 smd paste+0 mask+0: 1(-2.9,1.95) 2(-2.9,1.3) 3(-2.9,0.65) 4(-2.9,0) 5(-2.9,-0.65) 6(-2.9,-1.3) 7(-2.9,-1.95) 8(2.9,-1.95) 9(2.9,-1.3) 10(2.9,-0.65) 11(2.9,0) 12(2.9,0.65) 13(2.9,1.3) 14(2.9,1.95)
  silkscreen extent -4.32,-2.55 2.25,2.55, body extent -3.2,-2.5 3.2,2.5, height 1.2
RESCAXS_EXB-2HV [mm] "Panasonic Resistor Array"
  rect 0.425x0.5 smd mask+0.07: 1(-1.838,-0.75) 8(1.837,-0.75) 9(1.837,0.75) 16(-1.837,0.75)
  rect 0.25x0.5 smd mask+0.07: 2(-1.25,-0.75) 3(-0.75,-0.75) 4(-0.25,-0.75) 5(0.25,-0.75) 6(0.75,-0.75) 7(1.25,-0.75) 10(1.25,0.75) 11(0.75,0.75) 12(0.25,0.75) 13(-0.25,0.75) 14(-0.75,0.75) 15(-1.25,0.75)
  silkscreen extent -2.05,-0.25 2.05,0.25, body extent -1.95,-0.8 1.95,0.8, height 0.55
RHB0032N-MFG [mm]
  rrect40% 0.6x0.25 smd paste+0 mask+0: 1(-2.4,1.75) 2(-2.4,1.25) 3(-2.4,0.75) 4(-2.4,0.25) 5(-2.4,-0.25) 6(-2.4,-0.75) 7(-2.4,-1.25) 8(-2.4,-1.75) 17(2.4,-1.75) 18(2.4,-1.25) 19(2.4,-0.75) 20(2.4,-0.25) 21(2.4,0.25) 22(2.4,0.75) 23(2.4,1.25) 24(2.4,1.75)
  rrect40% 0.25x0.6 smd paste+0 mask+0: 9(-1.75,-2.4) 10(-1.25,-2.4) 11(-0.75,-2.4) 12(-0.25,-2.4) 13(0.25,-2.4) 14(0.75,-2.4) 15(1.25,-2.4) 16(1.75,-2.4) 25(1.75,2.4) 26(1.25,2.4) 27(0.75,2.4) 28(0.25,2.4) 29(-0.25,2.4) 30(-0.75,2.4) 31(-1.25,2.4) 32(-1.75,2.4)
  rrect3% 3.45x3.45 smd paste-1000 mask+0: 33(0,0)
  silkscreen extent -3.4,-2.55 2.55,2.55, body extent -2.8,-2.8 2.8,2.8, height 0.25
Samtec_FTSH-105-01-x-DV-K [mm] "Header(Shrouded), 1.27mm, 5x2, SMT"
  rect 2.79x0.74 smd: 1(-2.035,2.54) 2(2.035,2.54) 3(-2.035,1.27) 4(2.035,1.27) 5(-2.035,0) 6(2.035,0) 7(-2.035,-1.27) 8(2.035,-1.27) 9(-2.035,-2.54) 10(2.035,-2.54)
  silkscreen extent -3.73,-3.48 3.73,3.48, body extent -2.92,-3.18 2.92,3.17, height 6.13
SW_TL1015AF160QG [mm] "E-Switch"
  rect 0.95x1.4 smd: 1(-2.1,0) 2(2.1,0)
  silkscreen extent -2,-1.5 2,1.5, body extent -2.3,-1.5 2.3,1.5, height 2
TE_2-5747706-0 [mil] "Receptacle, D-SUB-9, 2.74mm, TH"
  rrect50% 61.5x61.5 hole 41: 1(216,56)
  round 61.5 hole 41: 2(108,56) 3(0,56) 4(-108,56) 5(-216,56) 6(162,-56) 7(54,-56) 8(-54,-56) 9(-162,-56)
  round 181.5 hole 121: 10(492,0) 11(-492,0)
  body extent -606,-248 607,248, height 479
TI_Stacked_Overlay_Small [mil]
  silkscreen extent -418,-98 418,98
TNPV1206 [mm] "VISHAY"
  rrect11% 0.9x1.7 smd: 1(-1.6,0) 2(1.6,0)
  silkscreen extent -2.4,-1.2 2.4,1.2, body extent -1.67,-0.87 1.67,0.87, height 0.65
WEEE_Minimum [mil] "WEEElie bin"
  silkscreen extent -95,-172 99,104

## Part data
C1 C4 C10 C12 C15 C17: library part CMP-0084283-1, "CAP, CERM, 10 pF, 100 V,+/- 5%, C0G/NP0, AEC-Q200 Grade 1, 0603", Cap_Case=0603, Manufacturer=MuRata, TempCo=C0G/NP0, Tolerance_%=5%, Value2=100V, ValueDisplayed=10pF
C2 C11 C18: library part CMP-0084514-1, "CAP, CERM, 6800 pF, 100 V,+/- 5%, C0G/NP0, AEC-Q200 Grade 0, 0603", Cap_Case=0603, Manufacturer=TDK, TempCo=C0G/NP0, Tolerance_%=5%, Value2=100V, ValueDisplayed=6800pF
C3 C7: library part CMP-0007502-5, "CAP, CERM, 2.2 uF, 50 V, +/- 10%, X5R, AEC-Q200 Grade 3, 0603", Cap_Case=0603, Manufacturer=MuRata, Supplier Part Number 1=490-12332-1-ND, TempCo=X5R, Tolerance_%=10%, Value1=Unknown, Value2=50V, ValueDisplayed=2.2uF
C5: library part CMP-0090362-1, "0.1µF ±10% 10V Ceramic Capacitor X7R 0402 (1005 Metric)", Digikey Part Number=732-7513-1-ND, Manufacturer="Wurth Electronics", Mouser Part Number=710-885012205018, Operating Temperature Range="-55°C to +125°C", TempCo=15%, Temperature Characteristic=X7R, Tolerance_%=10%, ValueDisplayed=0.1uF
C6 C9: library part CMP-0006420-2, "CAP, CERM, 15 pF, 50 V, +/- 5%, C0G/NP0, 0402", Cap_Case=0402, Manufacturer=MuRata, Supplier Part Number 1=81-GRM1555C1H150JA1D, TempCo=C0G/NP0, Tolerance_%=5%, Value1=Unknown, Value2=50V, ValueDisplayed=15pF
C8: library part CMP-0082113-1, "CAP, CERM, 1 µF, 25 V,+/- 20%, X7R, AEC-Q200 Grade 1, 0603", Cap_Case=0603, Manufacturer=TDK, Supplier Part Number 1=445-12548-2-ND, TempCo=X7R, Tolerance_%=20%, Value2=25V, ValueDisplayed=1µF
C13 C16 C19 C20 C21 C35: library part CMP-0007090-4, "CAP, CERM, 0.1 uF, 25 V, +/- 10%, X8R, AEC-Q200 Grade 0, 0603", Cap_Case=0603, Manufacturer=TDK, Supplier Part Number 1=445-5885-1-ND, TempCo=X8R, Tolerance_%=10%, Value1=Unknown, Value2=25V, ValueDisplayed=0.1uF
C14 C34: library part CMP-0086193-1, "CAP, CERM, 10 µF, 10 V,+/- 10%, X5R, 0603", Cap_Case=0603, Manufacturer=MuRata, TempCo=X5R, Tolerance_%=10%, Value2=10V, ValueDisplayed=10µF
C22 C26 C29 C32 C37 C42: library part CMP-0008921-2, "CAP, CERM, 0.068 uF, 50 V, +/- 5%, C0G/NP0, 1206", Cap_Case=1206, Manufacturer=MuRata, Supplier Part Number 1=490-3360-1-ND, TempCo=C0G/NP0, Tolerance_%=5%, Value1="0.01 ohm", Value2=50V, ValueDisplayed=0.068uF
C23 C44: library part CMP-0124278-2, "1 µF ±20% 10V Ceramic Capacitor X7R 0402 (1005 Metric)", Digikey Part Number=478-KAM05CR71A105MHCT-ND, Manufacturer="KYOCERA AVX", Operating Temperature Range="-55°C to +125°C", TempCo=15%, Temperature Characteristic=X7R, Tolerance_%=20%, ValueDisplayed=1uF
C24 C27 C31 C36 C39 C43: library part CMP-0006608-2, "CAP, CERM, 1 uF, 25 V, +/- 10%, X5R, 0402", Cap_Case=0402, Manufacturer=MuRata, Supplier Part Number 1=490-10017-1-ND, TempCo=X5R, Tolerance_%=10%, Value1=Unknown, Value2=25V, ValueDisplayed=1uF
C25 C28: library part CMP-0006979-5, "CAP, CERM, 0.1 uF, 25 V, +/- 10%, X7R, 0603", Cap_Case=0603, Manufacturer=Kemet, Supplier Part Number 1=399-5345-1-ND, TempCo=X7R, Tolerance_%=10%, Value1=Unknown, Value2=25V, ValueDisplayed=0.1uF
C30: library part CMP-0092769-1, "Cap Ceramic 220nF 16V X7R 10% Pad SMD 0402 +125°C Automotive T/R", Manufacturer="TDK Corporation", Operating Temperature Range="-55°C to +125°C", TempCo=15%, Temperature Characteristic=X7R, Tolerance_%=0.1%, ValueDisplayed=220nF
C33: library part CMP-0007328-5, "CAP, CERM, 0.47 uF, 10 V, +/- 10%, X5R, 0603", Cap_Case=0603, Manufacturer=MuRata, Supplier Part Number 1=490-1539-1-ND, TempCo=X5R, Tolerance_%=10%, Value1=Unknown, Value2=10V, ValueDisplayed=0.47uF
C38: library part CMP-0090363-1, "10000pF ±10% 25V Ceramic Capacitor X7R 0402 (1005 Metric)", Digikey Part Number=732-7545-1-ND, Manufacturer="Wurth Electronics", Mouser Part Number=710-885012205050, Operating Temperature Range="-55°C to +125°C", TempCo=15%, Temperature Characteristic=X7R, Tolerance_%=10%, ValueDisplayed=10nF
C40 C41: library part CMP-0079607-1, "CAP, CERM, 1 µF, 16 V,+/- 10%, X7R, AEC-Q200 Grade 1, 0603", Cap_Case=0603, Manufacturer=TDK, Supplier Part Number 1=445-12539-1-ND, TempCo=X7R, Tolerance_%=10%, Value2=16V, ValueDisplayed=1µF
D1 D2: library part CMP-0076982-2, "Diode, Switching, 75 V, 0.3 A, SOD-523F", Manufacturer="Fairchild Semiconductor", Value1=0.3A, Value2=V
D3 D4: library part CMP-0084855-1, "LED, Red, SMD", Color=Red, Manufacturer="Visual Communications Company, LLC", Power_TotalModule=100mW, Value1=0.1W, Value2=1.7V
J1 J9 J10: library part CMP-0123060-1, "3 Position Wire to Board Terminal Block Horizontal with Board 0.100\" (2.54mm) Through Hole", Current_A=6A, Digikey Part Number=732-691210910003-ND, Manufacturer=Wurth, Mouser Part Number=710-691210910003, Operating Temperature Range="-40°C to +105°C", Voltage_V=150V
J2 J3 J4 J7: library part CMP-0074910-1, "Terminal Block, 5.08 mm, 2x1, Brass, TH", Color=Blue, Current_A=15A, Manufacturer="On-Shore Technology", Supplier Part Number 1=ED1609-ND, Voltage_V=300V
J5 J6: library part CMP-0075197-1, "Header, 2.54mm, 2x1, TH", Color=Black, Current_A=2A, Manufacturer=3M, Supplier Part Number 1=3M9447-ND, Voltage_V=1kV
J8: library part CMP-0075634-1, "Header(Shrouded), 1.27mm, 5x2, Gold, SMT", Color=Black, Current_A=3.3A, Manufacturer=Samtec, Supplier Part Number 1=SAM8799-ND
Logo1: library part CMP-0074838-1, "Texas Instrument Corporate Signature"
Logo2: library part CMP-0074844-1
Logo3: library part CMP-0074847-1, "FCC_disclaimer"
Logo4: library part CMP-0074769-1
R1 R2 R3 R4 R11 R12 R13 R14 R21 R22 R23 R24: library part CMP-0018811-2, "RES, 330 k, 0.1%, 1 W, 1206", Manufacturer="Vishay Draloric", Power_W=1W, Supplier Part Number 1=541-2312-1-ND, TempCo="25 ppm/C", Tolerance_%=0.1%, Value_Code=330k
R5 R10 R15 R18 R25 R28: library part CMP-0084355-1, "RES, 1.00 k, 0.5%, 0.1 W, 0603", Manufacturer=Yageo, Power_W=100mW, TempCo="25 ppm/C", Tolerance_%=0.5%, Value2=0.1W, Value_Code=1k00, ValueDisplayed=1.00k
R6 R7: library part CMP-0026736-1, "RES, 470, 1%, 0.063 W, 0402", Manufacturer="Yageo America", Power_W=63mW, Supplier Part Number 1=311-470LRCT-ND, TempCo="100 ppm/C", Tolerance_%=1%, Value2=0.063W, Value_Code=470R, ValueDisplayed=470
R8 R16 R26: library part CMP-0126415-1, "430 V 4.5 kA Varistor 1 Circuit Through Hole Disc 14mm", Clamping Voltage=710V, Digikey Part Number=732-13275-1-ND, Manufacturer="Wurth Electronics", Mouser Part Number=710-820542711, Operating Temperature Range="-40°C to +105°C", ValueDisplayed=450pF, Varistor Voltage=430V, Voltage Tolerance=10%
R9 R17 R27: library part CMP-0022895-5, "RES, 1.00 k, 1%, 0.1 W, 0603", Manufacturer=Yageo, Power_W=100mW, Supplier Part Number 1=311-1.00KHRCT-ND, TempCo="100 ppm/C", Tolerance_%=1%, Value2=0.1W, Value_Code=1k00, ValueDisplayed=1.00k
R19 R20 R45: library part CMP-0026935-3, "RES, 47 k, 5%, 0.063 W, AEC-Q200 Grade 0, 0402", Manufacturer=Vishay-Dale, Power_W=63mW, Supplier Part Number 1=541-47KJCT-ND, TempCo="200 ppm/C", Tolerance_%=5%, Value2=0.063W, Value_Code=47k0, ValueDisplayed=47k
R29: library part CMP-0025817-4, "RES, 4.7 k, 5%, 0.1 W, AEC-Q200 Grade 0, 0603", Manufacturer=Vishay-Dale, Power_W=100mW, Supplier Part Number 1=541-4.7KGCT-ND, TempCo="200 ppm/C", Tolerance_%=5%, Value2=0.1W, Value_Code=4k70, ValueDisplayed=4.7k
R30: library part CMP-0081256-1, "RES, 10 k, 5%, 0.063 W, AEC-Q200 Grade 1, Resistor Array - 8x1", Manufacturer=Panasonic, Power_W=63mW, Supplier Part Number 1=Y1103CT-ND, TempCo="200 ppm/C", Tolerance_%=5%, Value2=0.063W, Value_Code=10k0, ValueDisplayed=10k
R31 R37 R39 R43 R46 R50: library part CMP-0026757-1, "RES, 1.00 M, 1%, 0.063 W, AEC-Q200 Grade 0, 0402", Manufacturer="Stackpole Electronics Inc", Power_W=63mW, Supplier Part Number 1=RMCF0402FT1M00CT-ND, TempCo="100 ppm/C", Tolerance_%=1%, Value2=0.063W, Value_Code=1M00, ValueDisplayed=1.00M
R32 R36: library part CMP-0026815-1, "RES, 100 k, 0.1%, 0.063 W, 0402", Manufacturer="Susumu Co Ltd", Power_W=63mW, Supplier Part Number 1=RG10P100KBCT-ND, TempCo="25 ppm/C", Tolerance_%=0.1%, Value2=0.063W, Value_Code=100k
R33 R34 R40 R41 R47 R48: library part CMP-0026770-1, "RES, 1.00 k, 0.1%, 0.063 W, 0402", Manufacturer=Panasonic, Power_W=63mW, Supplier Part Number 1=P1.0KDCCT-ND, TempCo="25 ppm/C", Tolerance_%=0.1%, Value2=0.063W, Value_Code=1k00, ValueDisplayed=1.00k
R35 R38 R42 R44 R49 R51: library part CMP-0026280-2, "RES, 301 k, 1%, 0.063 W, AEC-Q200 Grade 0, 0402", Manufacturer=Vishay-Dale, Power_W=63mW, Supplier Part Number 1=541-301KLCT-ND, TempCo="100 ppm/C", Tolerance_%=1%, Value2=0.063W, Value_Code=301k
R52 R53: library part CMP-0026797-1, "RES, 10.0 k, 0.1%, 0.063 W, 0402", Manufacturer="TT Electronics/IRC", Power_W=63mW, Supplier Part Number 1=985-1366-1-ND, TempCo="10 ppm/C", Tolerance_%=0.1%, Value2=0.063W, Value_Code=10k0, ValueDisplayed=10.0k
RS1: library part CMP-0079577-1, "Receptacle, D-SUB-9, 2.74mm, Gold, TH", Color=Black, Current_A=6A, Manufacturer="TE Connectivity", Supplier Part Number 1=A32036-ND, Voltage_V=125V
SW1 SW2: library part CMP-0120713-1, "Dip Switch SPST 3 Position Surface Mount Slide (Standard) Actuator 25mA 24VDC", Coil Resistance_ohm=100mΩ, Contact Current Rating=25mA, Digikey Part Number=732-416131160803CT-ND, Manufacturer="Wurth Electronics", Mouser Part Number=710-416131160803, Operating Temperature Range="-40°C to +85°C"
SW3: library part CMP-0122841-1, "Dip Switch SPST 1 Position Surface Mount Slide (Standard) Actuator 25mA 24VDC", Coil Resistance_ohm=100mΩ, Contact Current Rating=25mA, Digikey Part Number=CKN10538CT-ND, Manufacturer="C&K Components", Mouser Part Number=611-TDA01H0SB1R, Operating Temperature Range="-40°C to +85°C"
SW4: library part CMP-0002143-2, "Switch, Tactile, SPST-NO, 0.05A, 12V, SMT", CurrentRating_mA=50A, Manufacturer=E-Switch, Supplier Part Number 1=EG4344CT-ND
U1: library part CMP-0073793-1, "150-mA, 30-V, Ultra-Low IQ, Wide Input Low-Dropout Regulator with Reverse Current Protection, DBV0005A (SOT-23-5)", Alternate Manufacturer="Texas Instruments", Alternate PartNumber=TPS70933DBVT
U2: library part CMP-0044119-1, "3-V to 5.5-V Multichannel RS-232 Line Driver / Receiver with ±15-kV IEC ESD Protection, -40 to 85 degC, 16-Pin SSOP (DB), Green (RoHS & no Sb/Br)", Drivers Per Package=2, Supply Voltage(s)(V)="3.3 or 5.0"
